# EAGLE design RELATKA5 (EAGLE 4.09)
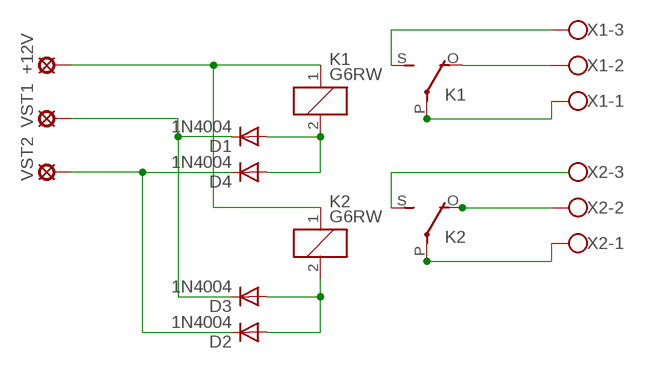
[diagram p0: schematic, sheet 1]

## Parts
+12V  LSP13  [LSP13]
D1  1N4004  [DO41-10]
D2  1N4004  [DO41-10]
D3  1N4004  [DO41-10]
D4  1N4004  [DO41-10]
K1  G6RW  [G6RW]
K2  G6RW  [G6RW]
VST1  LSP13  [LSP13]
VST2  LSP13  [LSP13]
X1  AK300/3  [AK300/3]
X2  AK300/3  [AK300/3]

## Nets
N$1: +12V.MP K1.1 K2.1
N$2: D1.A D4.A K1.2
N$3: K1.O(2:O) X1.2
N$5: K1.S(2:S) X1.3
N$7: K1.P(2:P) X1.1
N$8: K2.S(2:S) X2.3
N$9: K2.O(2:O) X2.2
N$10: K2.P(2:P) X2.1
N$29: D2.A D3.A K2.2
N$32: D1.C D3.C VST1.MP
N$34: D2.C D4.C VST2.MP

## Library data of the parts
+12V VST1 VST2 = solpad:LSP13: SOLDER PAD
D1-D4 = diode:1N4004: DIODE
K1 K2 = relay:G6RW: RELAY 1 x switch, Omron
X1 X2 = con-ptr500:AK300/3: CONNECTOR

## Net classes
0 default: clearance 1 mm

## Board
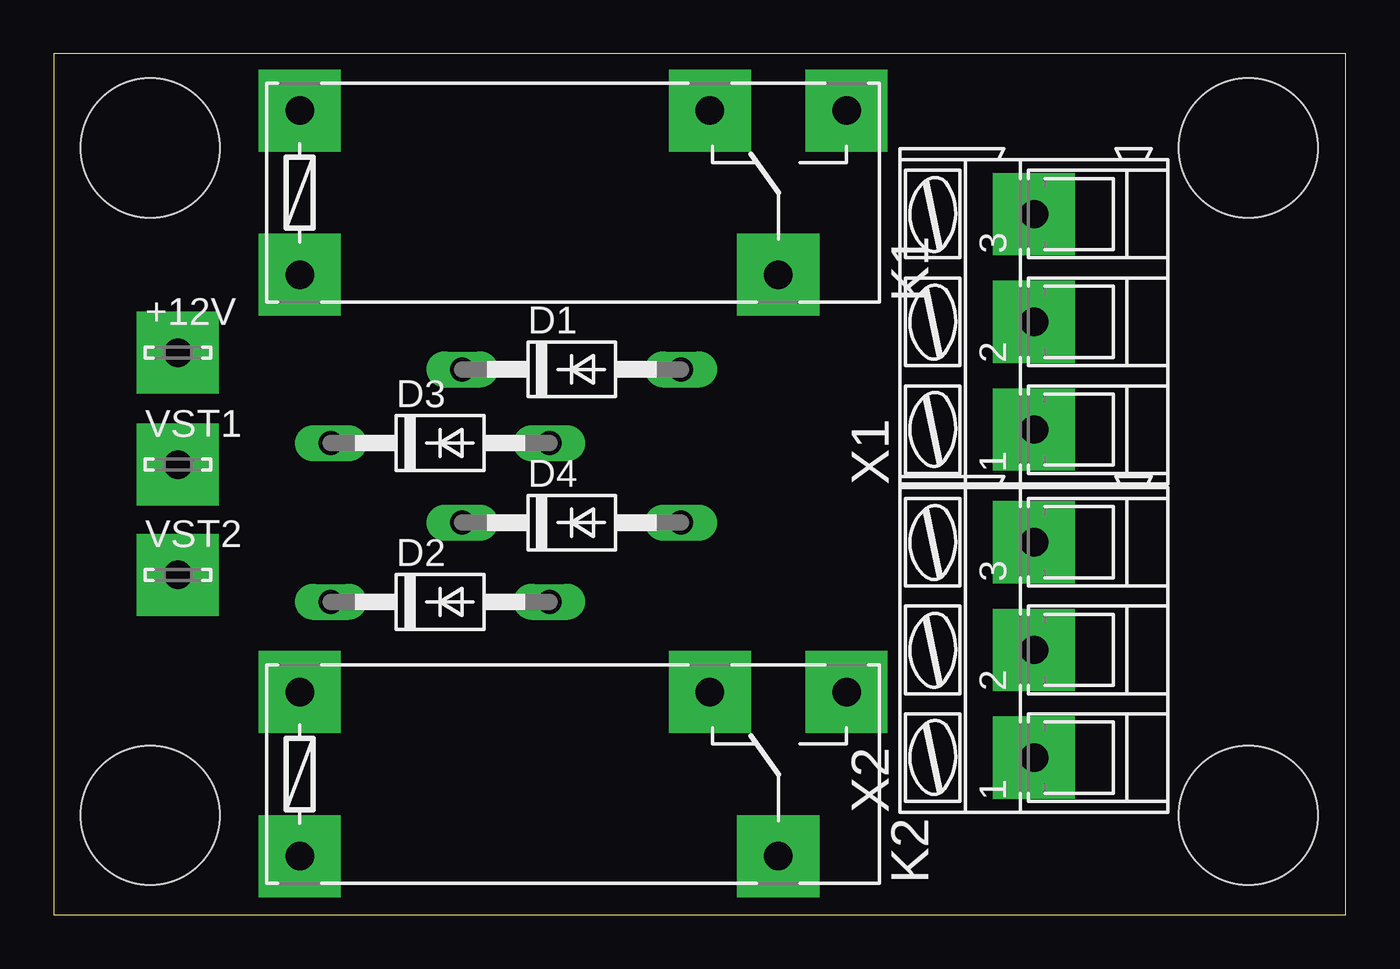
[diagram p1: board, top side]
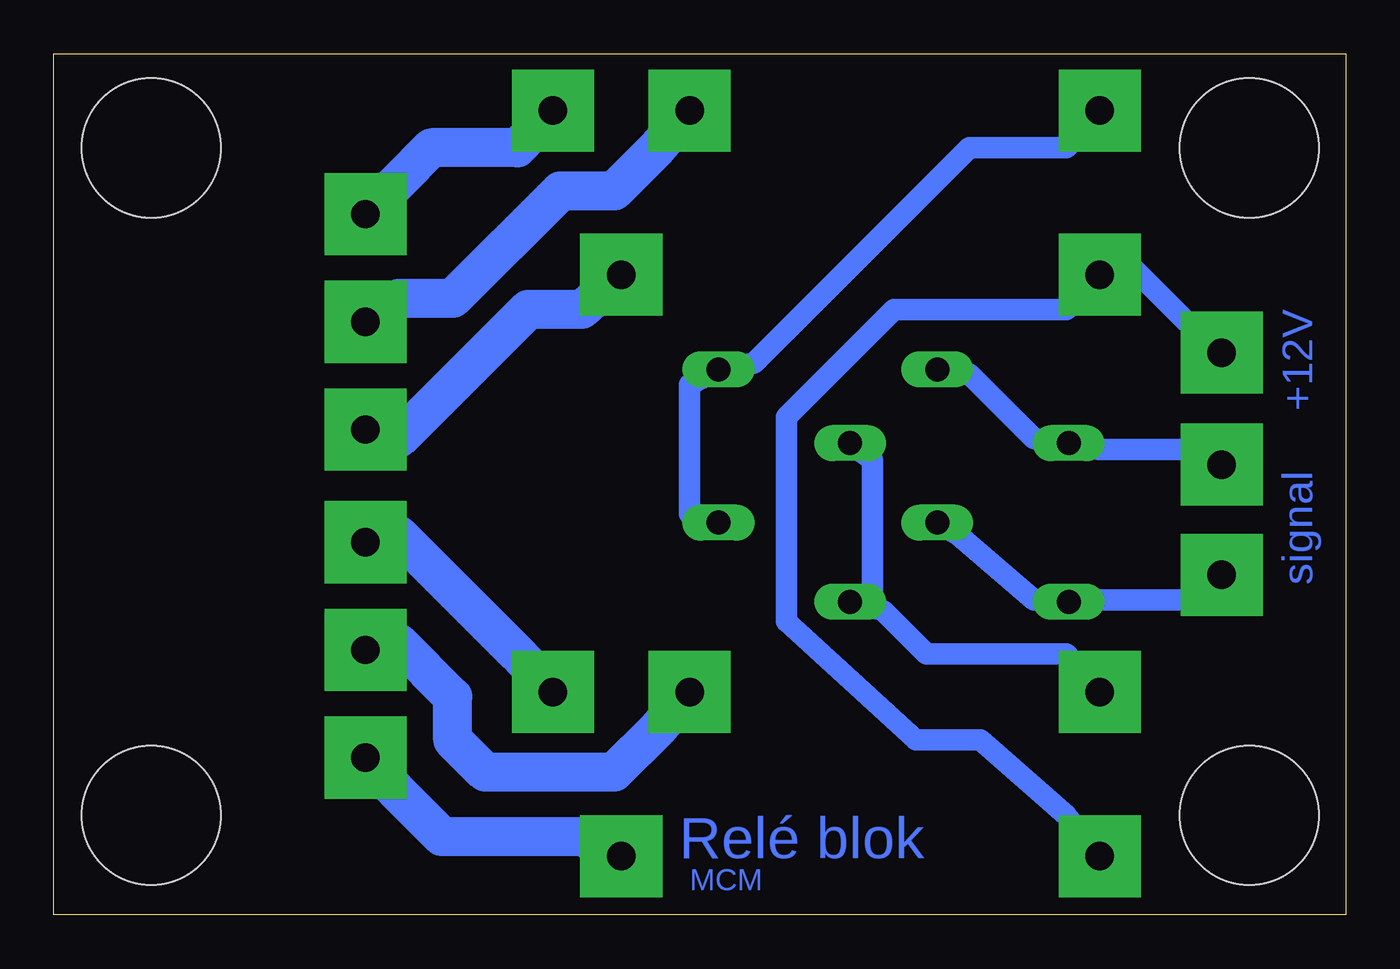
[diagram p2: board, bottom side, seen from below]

Size 60 x 40 mm. Coordinates in mm from the lower left corner, seen from the top.
Outline: 0,0 60,0 60,40 0,40 0,0
Copper layers used: Bottom
Holes 6.45 mm at 4.47,35.63 4.47,4.63 55.47,4.63 55.47,35.63

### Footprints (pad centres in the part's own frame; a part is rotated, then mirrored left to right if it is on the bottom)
LSP13 = drill 1.321 pad 3.81 square: MP 0,0
DO41-10 = drill 1.118 long: A 5.08,0; C -5.08,0
G6RW = drill 1.321 pad 3.81 square: 1 -12.7,-3.81; 2 -12.7,3.81; O 6.35,3.81; P 9.525,-3.81; S 12.7,3.81
AK300/3 = drill 1.321 pad 3.81 square: 1 -5.004,0; 2 0,0; 3 5.004,0

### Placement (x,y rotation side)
+12V  5.76,26.12 0 top
D1  24.05,25.34 0 top
D2  17.94,14.54 0 top
D3  17.94,21.92 0 top
D4  24.05,18.22 0 top
K1  24.12,33.55 0 top
K2  24.12,6.54 0 top
VST1  5.76,20.92 0 top
VST2  5.76,15.8 0 top
X1  45.52,27.55 90 top
X2  45.52,12.31 90 top

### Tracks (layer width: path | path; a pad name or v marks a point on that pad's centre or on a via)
N$1
  Bottom 1: +12V.MP 7.47,27.63 9.97,30.13 K1.1 12.97,28.13 20.97,28.13 25.97,23.13 25.97,13.63 19.97,8.13 16.97,8.13 12.97,4.63 K2.1
N$2
  Bottom 1: D4.A 30.47,18.63 30.47,24.63 D1.A 27.47,25.63 17.47,35.63 12.97,35.63 K1.2
N$3
  Bottom 1.8: K1.O 31.97,35.63 33.97,33.63 36.47,33.63 41.47,28.63 43.97,28.63 X1.2
N$5
  Bottom 1.8: K1.S 38.47,35.63 42.47,35.63 43.97,34.13 X1.3
N$7
  Bottom 1.8: K1.P 35.47,28.13 37.97,28.13 43.97,22.13 X1.1
N$8
  Bottom 1.8: K2.S 38.47,12.13 43.97,17.63 X2.3
N$9
  Bottom 1.8: K2.O 31.97,8.63 33.97,6.63 39.97,6.63 41.47,8.13 41.47,10.13 43.97,12.63 X2.2
N$10
  Bottom 1.8: K2.P 35.47,3.63 41.97,3.63 43.97,5.63 X2.1
N$29
  Bottom 1: D3.A 21.97,21.13 21.97,15.13 D2.A 21.47,14.13 19.47,12.13 12.97,12.13 K2.2
N$32
  Bottom 1: VST1.MP 7.47,21.63 11.47,21.63 D3.C 14.47,22.13 17.47,25.13 D1.C
N$34
  Bottom 1: VST2.MP 7.47,14.63 11.47,14.63 D2.C 14.47,14.63 17.97,17.63 D4.C

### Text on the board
Bottom: +12V | signal | Relé blok | MCM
